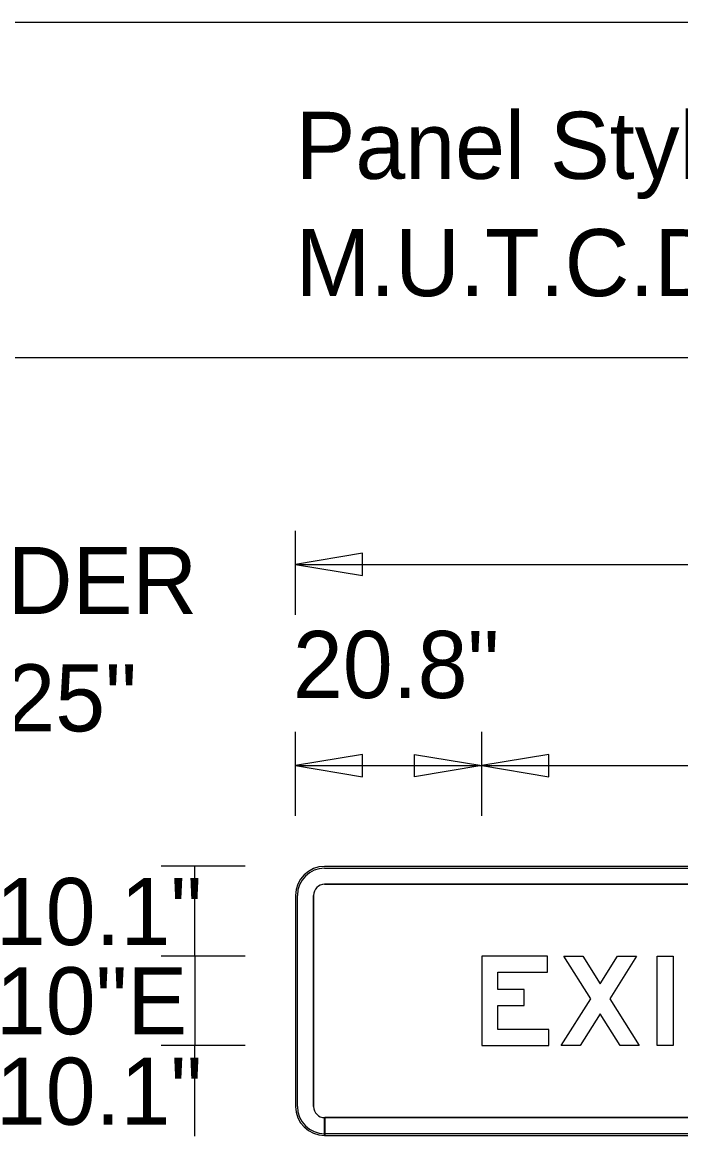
# Model space of a CAD drawing. Extents: x 1806251 to 1809821, y 414895 to 422886.
# Drawn here: x 1809676.959 to 1809677.695, y 415032.981 to 415034.226 of the extents above; entities that cross this region are included whole.
import ezdxf

# ---------------------------------------------------------------- set-up
doc = ezdxf.new("R2010")
doc.units = 0
for name, color, linetype in [('GSBWFILL', 7, 'Continuous'), ('GSCOLORFILL', 7, 'Continuous'), ('GSDIMS', 7, 'Continuous'), ('GSOUTLINE', 7, 'Continuous'), ('GSSHT', 7, 'Continuous')]:
    doc.layers.add(name, color=color, linetype=linetype)

msp = doc.modelspace()

# ---------------------------------------------------------------- linework, layer by layer
at = {"layer": 'GSBWFILL'}
for p, q in [((1809678.3731, 415033.2821), (1809677.2971, 415033.2821)), ((1809677.2971, 415033.2621), (1809678.3731, 415033.2621)), ((1809677.2646, 415033.2496), (1809677.2646, 415033.0136)), ((1809677.2846, 415033.0136), (1809677.2846, 415033.2496)), ((1809677.2971, 415032.9811), (1809677.2971, 415033.0011)), ((1809678.3731, 415033.0011), (1809677.2973, 415033.0011)), ((1809677.2973, 415033.0011), (1809677.2973, 415032.9811)), ((1809677.2973, 415032.9811), (1809678.3731, 415032.9811))]:
    msp.add_line(p, q, dxfattribs=at)
for points in [[(1809677.5476, 415033.0996), (1809677.4906, 415033.0996), (1809677.4906, 415033.1265), (1809677.5201, 415033.1265), (1809677.5201, 415033.1445), (1809677.4906, 415033.1445), (1809677.4906, 415033.1636), (1809677.5461, 415033.1636), (1809677.5461, 415033.1816), (1809677.4726, 415033.1816), (1809677.4726, 415033.0816), (1809677.5476, 415033.0816)], [(1809677.6273, 415033.0816), (1809677.6051, 415033.117), (1809677.5828, 415033.0816), (1809677.5616, 415033.0816), (1809677.5945, 415033.134), (1809677.5646, 415033.1816), (1809677.5858, 415033.1816), (1809677.6051, 415033.1509), (1809677.6243, 415033.1816), (1809677.6456, 415033.1816), (1809677.6157, 415033.134), (1809677.6486, 415033.0816)], [(1809677.6686, 415033.0816), (1809677.6686, 415033.1816), (1809677.6866, 415033.1816), (1809677.6866, 415033.0816)]]:
    msp.add_lwpolyline(points, close=True, dxfattribs=at)
for centre, radius, start, end in [((1809677.2971, 415033.2496), 0.0325, 90, 180), ((1809677.2971, 415033.2496), 0.0125, 90, 180), ((1809677.2971, 415033.0136), 0.0325, 180, 270), ((1809677.2971, 415033.0136), 0.0125, 180, 270)]:
    msp.add_arc(centre, radius, start, end, dxfattribs=at)
at = {"layer": 'GSCOLORFILL'}
for p, q in [((1809678.3731, 415033.2821), (1809677.2971, 415033.2821)), ((1809678.3731, 415033.2821), (1809677.2971, 415033.2821)), ((1809678.3731, 415033.2821), (1809677.2971, 415033.2821)), ((1809677.2971, 415033.2801), (1809678.3731, 415033.2801)), ((1809677.2971, 415033.2621), (1809678.3731, 415033.2621)), ((1809677.2646, 415033.2496), (1809677.2646, 415033.0136)), ((1809677.2646, 415033.2496), (1809677.2646, 415033.0136)), ((1809677.2646, 415033.2496), (1809677.2646, 415033.0136)), ((1809677.2666, 415033.0136), (1809677.2666, 415033.2496)), ((1809677.2846, 415033.0136), (1809677.2846, 415033.2496)), ((1809677.2971, 415032.9811), (1809677.2971, 415033.0011)), ((1809678.3731, 415033.0011), (1809677.2973, 415033.0011)), ((1809677.2973, 415033.0011), (1809677.2973, 415032.9811)), ((1809677.2971, 415032.9811), (1809677.2971, 415032.9831)), ((1809678.3731, 415032.9831), (1809677.2971, 415032.9831)), ((1809677.2971, 415032.9831), (1809677.2971, 415032.9811)), ((1809677.2971, 415032.9811), (1809678.3731, 415032.9811)), ((1809677.2971, 415032.9811), (1809678.3731, 415032.9811)), ((1809677.2973, 415032.9811), (1809678.3731, 415032.9811))]:
    msp.add_line(p, q, dxfattribs=at)
for points in [[(1809677.5476, 415033.0996), (1809677.4906, 415033.0996), (1809677.4906, 415033.1265), (1809677.5201, 415033.1265), (1809677.5201, 415033.1445), (1809677.4906, 415033.1445), (1809677.4906, 415033.1636), (1809677.5461, 415033.1636), (1809677.5461, 415033.1816), (1809677.4726, 415033.1816), (1809677.4726, 415033.0816), (1809677.5476, 415033.0816)], [(1809677.6273, 415033.0816), (1809677.6051, 415033.117), (1809677.5828, 415033.0816), (1809677.5616, 415033.0816), (1809677.5945, 415033.134), (1809677.5646, 415033.1816), (1809677.5858, 415033.1816), (1809677.6051, 415033.1509), (1809677.6243, 415033.1816), (1809677.6456, 415033.1816), (1809677.6157, 415033.134), (1809677.6486, 415033.0816)], [(1809677.6686, 415033.0816), (1809677.6686, 415033.1816), (1809677.6866, 415033.1816), (1809677.6866, 415033.0816)]]:
    msp.add_lwpolyline(points, close=True, dxfattribs=at)
for centre, radius, start, end in [((1809677.2971, 415033.2496), 0.0325, 90, 180), ((1809677.2971, 415033.2496), 0.0325, 90, 180), ((1809677.2971, 415033.2496), 0.0325, 90, 180), ((1809677.2971, 415033.2496), 0.0305, 90, 180), ((1809677.2971, 415033.2496), 0.0125, 90, 180), ((1809677.2971, 415033.0136), 0.0325, 180, 270), ((1809677.2971, 415033.0136), 0.0325, 180, 270), ((1809677.2971, 415033.0136), 0.0325, 180, 270), ((1809677.2971, 415033.0136), 0.0305, 180, 270), ((1809677.2971, 415033.0136), 0.0125, 180, 270)]:
    msp.add_arc(centre, radius, start, end, dxfattribs=at)
at = {"layer": 'GSDIMS'}
for p, q in [((1809677.2645, 415033.5636), (1809677.2645, 415033.6574)), ((1809677.2645, 415033.6199), (1809678.4065, 415033.6199)), ((1809677.2645, 415033.3386), (1809677.2645, 415033.4324)), ((1809677.4726, 415033.3386), (1809677.4726, 415033.4324)), ((1809677.4726, 415033.3386), (1809677.4726, 415033.4324)), ((1809677.2645, 415033.3949), (1809677.4726, 415033.3949)), ((1809677.4726, 415033.3949), (1809678.1975, 415033.3949)), ((1809677.2082, 415033.2824), (1809677.1145, 415033.2824)), ((1809677.152, 415033.1816), (1809677.152, 415033.2824)), ((1809677.2082, 415033.1816), (1809677.1145, 415033.1816)), ((1809677.2082, 415033.1816), (1809677.1145, 415033.1816)), ((1809677.152, 415033.1816), (1809677.152, 415033.0816)), ((1809677.2082, 415033.0816), (1809677.1145, 415033.0816)), ((1809677.2082, 415033.0816), (1809677.1145, 415033.0816)), ((1809677.152, 415032.9804), (1809677.152, 415033.0816))]:
    msp.add_line(p, q, dxfattribs=at)
for points in [[(1809677.2645, 415033.6199), (1809677.3395, 415033.6074), (1809677.3395, 415033.6324)], [(1809677.2645, 415033.3949), (1809677.3395, 415033.3824), (1809677.3395, 415033.4074)], [(1809677.4726, 415033.3949), (1809677.3976, 415033.3824), (1809677.3976, 415033.4074)], [(1809677.4726, 415033.3949), (1809677.5476, 415033.3824), (1809677.5476, 415033.4074)]]:
    msp.add_lwpolyline(points, close=True, dxfattribs=at)
at = {"layer": 'GSOUTLINE'}
for p, q in [((1809678.3731, 415033.2821), (1809677.2971, 415033.2821)), ((1809678.3731, 415033.2621), (1809677.2971, 415033.2621)), ((1809677.2646, 415033.2496), (1809677.2646, 415033.0136)), ((1809677.2846, 415033.2496), (1809677.2846, 415033.0136)), ((1809677.2971, 415033.0011), (1809678.3731, 415033.0011)), ((1809677.2971, 415032.9811), (1809678.3731, 415032.9811))]:
    msp.add_line(p, q, dxfattribs=at)
for points in [[(1809677.5476, 415033.0996), (1809677.4906, 415033.0996), (1809677.4906, 415033.1265), (1809677.5201, 415033.1265), (1809677.5201, 415033.1445), (1809677.4906, 415033.1445), (1809677.4906, 415033.1636), (1809677.5461, 415033.1636), (1809677.5461, 415033.1816), (1809677.4726, 415033.1816), (1809677.4726, 415033.0816), (1809677.5476, 415033.0816)], [(1809677.6273, 415033.0816), (1809677.6051, 415033.117), (1809677.5828, 415033.0816), (1809677.5616, 415033.0816), (1809677.5945, 415033.134), (1809677.5646, 415033.1816), (1809677.5858, 415033.1816), (1809677.6051, 415033.1509), (1809677.6243, 415033.1816), (1809677.6456, 415033.1816), (1809677.6157, 415033.134), (1809677.6486, 415033.0816)], [(1809677.6686, 415033.0816), (1809677.6686, 415033.1816), (1809677.6866, 415033.1816), (1809677.6866, 415033.0816)]]:
    msp.add_lwpolyline(points, close=True, dxfattribs=at)
for centre, radius, start, end in [((1809677.2971, 415033.2496), 0.0325, 90, 180), ((1809677.2971, 415033.2496), 0.0125, 90, 180), ((1809677.2971, 415033.0136), 0.0325, 180, 270), ((1809677.2971, 415033.0136), 0.0125, 180, 270)]:
    msp.add_arc(centre, radius, start, end, dxfattribs=at)
at = {"layer": 'GSSHT'}
msp.add_line((1809672.1349, 415034.2262), (1809684.8891, 415034.2262), dxfattribs=at)
msp.add_lwpolyline([(1809672.634, 415033.8512), (1809684.6381, 415033.8512), (1809684.6381, 415026.3475), (1809672.634, 415026.3475)], close=True, dxfattribs=at)

# ---------------------------------------------------------------- texts
at = {"layer": 'GSDIMS'}
for s, p in [('Panel Style: tab1.bsi', (1809677.2645, 415034.0511)), ('M.U.T.C.D.: 2009 Edition', (1809677.2645, 415033.9199)), ('BORDER', (1809676.7255, 415033.5644)), ('20.8"', (1809677.2616, 415033.4704)), ('R=3.25"', (1809676.7255, 415033.4331)), ('10.1"', (1809676.9295, 415033.1941)), ('10"E', (1809676.9295, 415033.0943)), ('10.1"', (1809676.9295, 415032.9931))]:
    msp.add_text(s, height=0.075, dxfattribs=at).set_placement(p)

doc.saveas('drawing.dxf')
